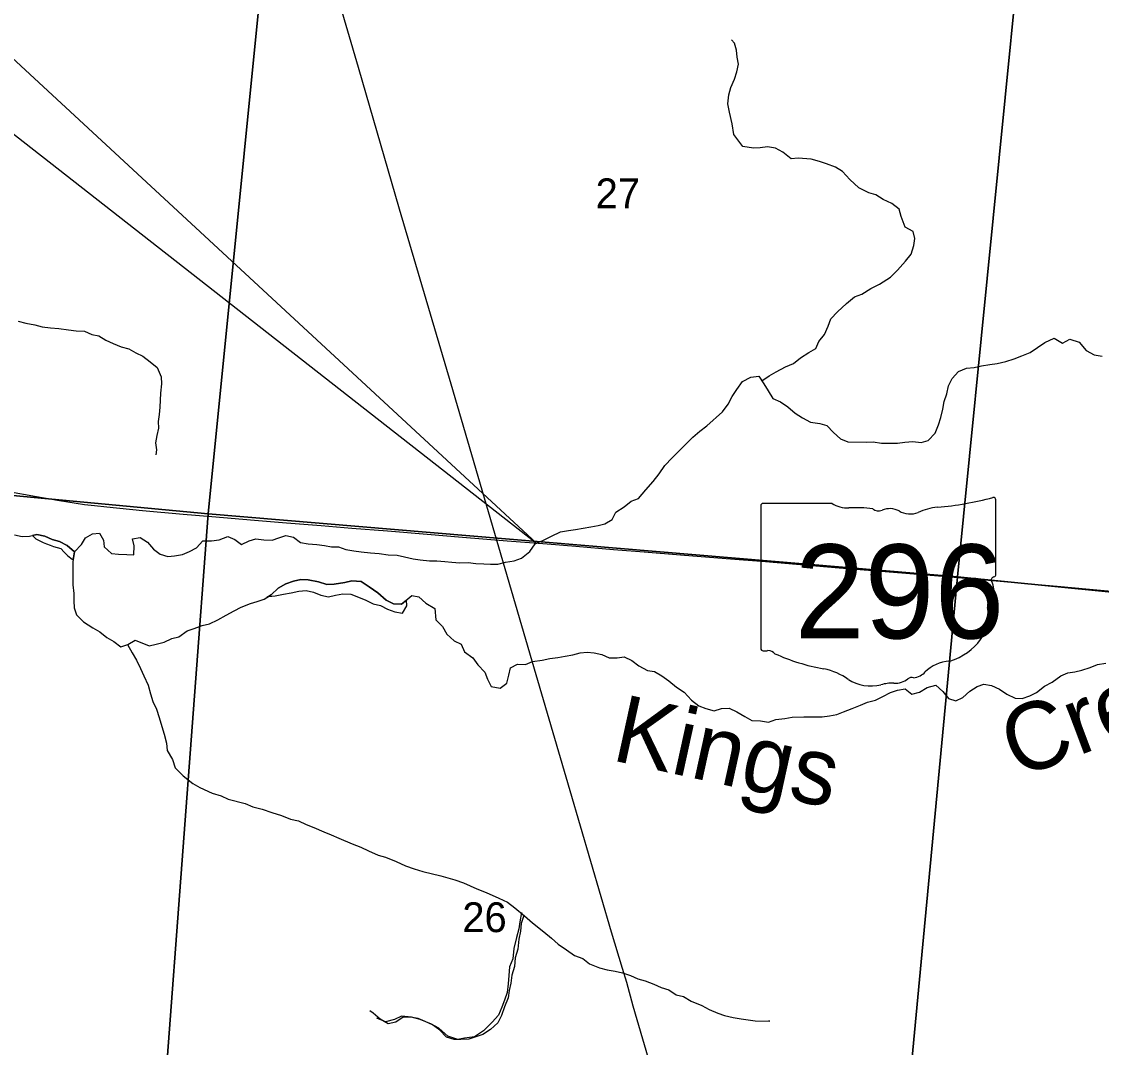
# Model space of a CAD drawing. Extents: x 831 to 1552, y 430 to 870.
# Drawn here: x 962.97 to 993.28, y 664.2 to 692.99 of the extents above; entities that cross this region are included whole.
import ezdxf

# ---------------------------------------------------------------- set-up
doc = ezdxf.new("R2010")
doc.units = 0
for name, color, linetype in [('GM_X_Corporation', 7, 'Continuous'), ('GM_X_Minor_Lake', 7, 'Continuous'), ('GM_X_Minor_River', 7, 'Continuous'), ('GM_X_Minor_River_Text', 7, 'Continuous'), ('GM_X_Rail_Line', 7, 'Continuous'), ('GM_X_Section_Text', 7, 'Continuous'), ('GM_X_State_Location', 7, 'Continuous'), ('GM_X_State_Route', 7, 'Continuous'), ('GM_X_State_Shield', 7, 'Continuous'), ('SH_Text', 7, 'Continuous')]:
    doc.layers.add(name, color=color, linetype=linetype)

msp = doc.modelspace()

# ---------------------------------------------------------------- linework, layer by layer
at = {"layer": 'GM_X_Corporation'}
for points in [[(970.228, 699.411), (968.2, 679.179), (947.656, 681.105), (949.612, 701.081)], [(970.228, 699.411), (991.236, 697.554), (989.239, 677.411), (968.2, 679.179)], [(1011.587, 695.769), (1009.676, 675.38), (989.239, 677.411), (991.236, 697.554)], [(947.656, 681.105), (968.2, 679.179), (966.669, 658.742), (945.863, 661.476)], [(968.2, 679.179), (989.239, 677.411), (987.314, 656.98), (966.669, 658.742)], [(989.239, 677.411), (1009.676, 675.38), (1007.707, 655.818), (987.314, 656.98)]]:
    msp.add_lwpolyline(points, close=True, dxfattribs=at)
at = {"layer": 'GM_X_Minor_Lake'}
for points in [[(964.455, 678.104), (964.248, 678.285), (964.031, 678.398), (963.828, 678.458), (963.618, 678.548), (963.391, 678.593), (963.275, 678.57)], [(963.275, 678.57), (963.371, 678.475), (963.568, 678.371), (963.664, 678.332), (963.765, 678.292), (963.863, 678.26), (963.968, 678.232), (964.068, 678.2), (964.159, 678.101), (964.256, 678.007), (964.352, 677.927), (964.411, 677.88)], [(964.411, 677.88), (964.455, 678.104)], [(973.769, 676.75), (973.633, 676.637), (973.406, 676.651), (973.204, 676.756), (972.968, 676.961), (972.722, 677.128), (972.498, 677.272), (972.241, 677.295), (972.042, 677.247), (971.737, 677.203), (971.532, 677.194), (971.299, 677.269), (971.012, 677.323), (970.808, 677.33), (970.601, 677.282), (970.387, 677.213), (970.171, 677.09), (969.968, 676.905), (969.848, 676.829)], [(969.848, 676.829), (969.898, 676.854), (970.088, 676.871), (970.317, 676.918), (970.531, 676.957), (970.753, 677.004), (970.958, 677.028), (971.162, 676.976), (971.364, 676.894), (971.583, 676.842), (971.781, 676.889), (971.988, 676.929), (972.207, 676.923), (972.425, 676.84), (972.627, 676.75), (972.837, 676.645), (973.04, 676.601), (973.242, 676.496), (973.445, 676.429), (973.657, 676.385), (973.776, 676.594), (973.769, 676.75)]]:
    msp.add_lwpolyline(points, dxfattribs=at)
at = {"layer": 'GM_X_Minor_River'}
for points in [[(983.743, 682.91), (983.946, 683.053), (984.146, 683.161), (984.408, 683.298), (984.631, 683.391), (984.833, 683.552), (985.065, 683.705), (985.258, 683.813), (985.348, 684.016), (985.505, 684.21), (985.603, 684.443), (985.685, 684.646), (985.865, 684.846), (986.122, 685.074), (986.348, 685.265), (986.548, 685.343), (986.803, 685.496), (987.049, 685.618), (987.359, 685.821), (987.554, 686.014), (987.781, 686.266), (987.932, 686.467), (988.007, 686.708), (988.035, 686.905), (987.988, 687.104), (987.771, 687.217), (987.651, 687.525), (987.596, 687.725), (987.396, 687.883), (987.149, 687.997), (986.948, 688.132), (986.745, 688.184), (986.468, 688.322), (986.217, 688.557), (986.011, 688.784), (985.809, 688.904), (985.562, 688.995), (985.366, 689.062), (985.125, 689.13), (984.762, 689.156), (984.564, 689.139), (984.334, 689.328), (984.125, 689.434), (983.906, 689.471), (983.7, 689.446), (983.51, 689.437), (983.208, 689.484), (982.96, 689.826), (982.915, 690.124), (982.834, 690.453), (982.788, 690.683), (982.818, 690.933), (982.877, 691.145), (982.975, 691.377), (983.042, 691.581), (983.086, 691.793), (983.054, 691.991), (983.037, 692.19), (982.982, 692.389), (982.893, 692.483)], [(962.868, 684.583), (963.087, 684.531), (963.336, 684.478), (963.547, 684.426), (963.781, 684.397), (964.008, 684.375), (964.28, 684.336), (964.5, 684.315), (964.735, 684.3), (964.937, 684.21), (965.133, 684.174), (965.327, 684.047), (965.537, 683.957), (965.762, 683.859), (965.973, 683.807), (966.174, 683.694), (966.369, 683.605), (966.576, 683.439), (966.777, 683.281), (966.883, 683.019), (966.893, 682.828), (966.862, 682.563), (966.85, 682.167), (966.829, 681.962), (966.801, 681.765), (966.81, 681.575), (966.759, 681.378), (966.73, 681.166), (966.755, 680.967), (966.736, 680.831)], [(975.716, 677.785), (975.944, 677.771), (976.133, 677.765), (976.331, 677.767), (976.552, 677.821), (976.796, 677.852), (977.003, 677.93), (977.229, 678.121), (977.379, 678.337), (977.595, 678.43), (977.841, 678.552), (978.095, 678.666), (978.316, 678.706), (978.514, 678.738), (978.728, 678.769), (978.942, 678.809), (979.148, 678.848), (979.339, 678.896), (979.54, 679.019), (979.644, 679.222), (979.876, 679.375), (980.078, 679.529), (980.285, 679.606), (980.49, 679.852), (980.694, 680.082), (980.867, 680.297), (981.018, 680.529), (981.23, 680.751), (981.425, 680.943), (981.613, 681.135), (981.808, 681.328), (982.003, 681.497), (982.204, 681.643), (982.641, 682.041), (982.799, 682.25), (982.912, 682.467), (983.039, 682.661), (983.205, 682.885), (983.436, 683.007), (983.657, 683.039), (983.802, 682.821), (983.926, 682.627), (984.056, 682.41), (984.273, 682.32), (984.474, 682.177), (984.681, 681.996), (984.89, 681.868), (985.107, 681.747), (985.371, 681.709), (985.567, 681.65), (985.759, 681.461), (985.951, 681.28), (986.161, 681.198), (986.677, 681.183), (986.867, 681.2), (987.101, 681.155), (987.336, 681.156), (987.556, 681.157), (987.755, 681.189), (987.983, 681.205), (988.217, 681.175), (988.416, 681.23), (988.612, 681.437), (988.702, 681.671), (988.769, 681.882), (988.821, 682.116), (988.866, 682.328), (988.94, 682.539), (988.985, 682.766), (989.089, 682.969), (989.262, 683.169), (989.485, 683.261), (989.706, 683.285), (989.912, 683.332), (990.148, 683.371), (990.354, 683.395), (990.598, 683.449), (990.828, 683.526), (991.043, 683.611), (991.274, 683.703), (991.483, 683.841), (991.692, 683.987), (991.954, 684.109), (992.185, 683.965), (992.393, 684.073), (992.656, 683.989), (992.847, 683.763), (993.071, 683.642), (993.297, 683.597)], [(962.769, 678.588), (962.987, 678.536), (963.185, 678.553), (963.391, 678.593), (963.618, 678.548), (963.828, 678.458), (964.031, 678.398), (964.248, 678.285), (964.455, 678.104), (964.651, 678.312), (964.763, 678.506), (964.955, 678.615), (965.153, 678.632), (965.269, 678.438), (965.286, 678.247), (965.493, 678.058), (965.69, 678.045), (965.918, 678.03), (966.115, 678.025), (966.13, 678.275), (966.082, 678.475), (966.296, 678.514), (966.497, 678.379), (966.666, 678.183), (966.859, 678.041), (967.07, 677.981), (967.26, 677.998), (967.481, 678.03), (967.681, 678.115), (967.874, 678.224), (968.054, 678.416), (968.297, 678.417), (968.51, 678.441), (968.756, 678.54), (968.95, 678.451), (969.144, 678.315), (969.352, 678.416), (969.543, 678.471), (969.762, 678.442), (969.997, 678.435), (970.189, 678.505), (970.388, 678.568), (970.6, 678.524), (970.792, 678.366), (971.012, 678.336), (971.254, 678.314), (971.473, 678.284), (971.669, 678.248), (971.859, 678.25), (972.069, 678.175), (972.296, 678.138), (972.5, 678.109), (972.757, 678.079), (973.007, 678.064), (973.257, 678.026), (973.507, 678.011), (973.718, 677.966), (973.959, 677.914), (974.156, 677.885), (974.42, 677.854), (974.625, 677.856), (974.845, 677.834), (975.042, 677.821), (975.269, 677.799), (975.504, 677.807), (975.716, 677.785)], [(964.455, 678.104), (964.401, 677.832), (964.409, 677.588), (964.403, 677.375), (964.405, 677.184), (964.436, 676.94), (964.43, 676.734), (964.447, 676.536), (964.51, 676.344), (964.709, 676.148), (964.97, 675.98), (965.163, 675.86), (965.356, 675.702), (965.558, 675.589), (965.751, 675.447), (965.95, 675.509), (966.159, 675.632), (966.548, 675.469), (966.74, 675.516), (966.969, 675.57), (967.185, 675.678), (967.376, 675.726), (967.616, 675.894), (967.815, 675.956), (968.038, 676.041), (968.244, 676.088), (968.475, 676.203), (968.706, 676.334), (968.938, 676.456), (969.13, 676.557), (969.391, 676.656), (969.583, 676.711), (969.775, 676.782), (969.968, 676.905), (970.171, 677.09), (970.387, 677.213), (970.601, 677.282), (970.808, 677.33), (971.012, 677.323), (971.299, 677.269), (971.532, 677.194), (971.737, 677.203), (972.042, 677.247), (972.241, 677.295), (972.498, 677.272), (972.722, 677.128), (972.968, 676.961), (973.204, 676.756), (973.406, 676.651), (973.633, 676.637), (973.921, 676.879), (974.118, 676.843), (974.31, 676.67), (974.564, 676.517), (974.592, 676.204), (974.784, 676.016), (974.899, 675.799), (975.106, 675.61), (975.301, 675.513), (975.401, 675.305), (975.631, 675.13), (975.777, 674.936), (975.969, 674.732), (976.047, 674.539), (976.147, 674.331), (976.396, 674.278), (976.59, 674.424), (976.642, 674.643), (976.693, 674.855), (976.886, 674.956), (977.113, 674.949), (977.306, 675.027), (977.58, 675.065), (977.794, 675.119), (978.022, 675.143), (978.228, 675.183), (978.442, 675.214), (978.641, 675.277), (978.839, 675.294), (979.043, 675.273), (979.254, 675.228), (979.464, 675.131), (979.684, 675.132), (979.882, 675.164), (980.092, 675.059), (980.292, 674.908), (980.532, 674.779), (980.728, 674.75), (980.937, 674.63), (981.138, 674.487), (981.353, 674.313), (981.561, 674.17), (981.775, 673.95), (981.975, 673.784), (982.17, 673.71), (982.411, 673.649), (982.61, 673.712), (982.831, 673.721), (983.04, 673.615), (983.264, 673.487), (983.466, 673.374)], [(965.942, 675.507), (966.072, 675.277), (966.188, 675.068), (966.302, 674.836), (966.395, 674.628), (966.524, 674.365), (966.585, 674.127), (966.655, 673.912), (966.755, 673.696), (966.831, 673.458), (966.9, 673.204), (966.969, 672.989), (967.038, 672.743), (967.055, 672.537), (967.207, 672.281), (967.276, 672.043), (967.505, 671.823), (967.771, 671.602), (967.966, 671.497), (968.318, 671.335), (968.566, 671.259), (968.761, 671.169), (969.243, 671.048), (969.46, 670.95), (969.716, 670.889), (969.994, 670.79), (970.258, 670.713), (970.513, 670.607), (970.739, 670.562), (970.956, 670.456), (971.174, 670.374), (971.451, 670.251), (971.653, 670.162), (971.871, 670.071), (972.246, 669.916), (972.486, 669.817), (972.703, 669.719), (972.98, 669.597), (973.183, 669.537), (973.484, 669.422), (973.746, 669.3), (973.986, 669.209), (974.234, 669.14), (974.739, 669.019), (975.123, 668.901), (975.371, 668.817), (975.746, 668.654), (976.008, 668.547), (976.36, 668.392), (976.608, 668.278), (976.815, 668.119), (977.082, 667.89), (977.304, 667.693), (977.623, 667.448), (977.838, 667.266), (978.03, 667.101), (978.261, 666.934), (978.484, 666.775), (978.717, 666.692), (978.91, 666.549), (979.187, 666.434), (979.406, 666.374), (979.625, 666.337), (979.836, 666.293), (980.061, 666.218), (980.264, 666.12), (980.467, 666.068), (980.715, 665.97), (980.917, 665.88), (981.135, 665.82), (981.336, 665.677), (981.547, 665.625), (981.763, 665.497), (982.056, 665.374), (982.265, 665.261), (982.505, 665.162), (982.7, 665.096), (982.941, 665.035), (983.16, 664.998), (983.357, 664.969), (983.561, 664.948), (983.971, 664.936), (983.941, 664.944)], [(983.466, 673.374), (983.708, 673.367), (983.935, 673.33), (984.142, 673.4), (984.393, 673.43), (984.592, 673.47), (984.926, 673.475), (985.176, 673.476), (985.434, 673.475), (985.648, 673.507), (985.846, 673.547), (986.038, 673.617), (986.276, 673.709), (986.514, 673.809), (986.714, 673.887), (986.936, 673.941), (987.144, 674.049), (987.359, 674.157), (987.551, 674.227), (987.765, 674.259), (987.958, 674.116), (988.172, 674.171), (988.381, 674.302), (988.633, 674.363), (988.825, 674.189), (988.986, 673.994), (989.189, 673.927), (989.382, 674.02), (989.584, 674.197), (989.786, 674.328), (989.977, 674.391), (990.189, 674.354), (990.413, 674.256), (990.622, 674.113), (990.854, 673.999), (991.051, 673.994), (991.266, 674.071), (991.458, 674.157), (991.676, 674.34), (991.891, 674.448), (992.139, 674.624), (992.332, 674.717), (992.53, 674.741), (992.729, 674.789), (992.959, 674.866), (993.166, 674.943), (993.402, 674.982)], [(977.065, 667.905), (976.985, 667.68), (976.971, 667.46), (976.926, 667.233), (976.895, 666.959), (976.82, 666.718), (976.798, 666.475), (976.73, 666.225), (976.7, 665.998), (976.657, 665.801), (976.628, 665.589), (976.522, 665.341), (976.439, 665.092), (976.334, 664.889), (976.131, 664.705), (975.915, 664.559), (975.715, 664.496), (975.524, 664.433), (975.296, 664.417), (975.106, 664.423), (974.896, 664.49), (974.704, 664.686), (974.503, 664.829), (974.293, 664.927), (974.099, 665.009), (973.887, 665.046), (973.675, 665.044), (973.473, 664.906), (973.252, 664.859), (973.028, 664.988), (972.835, 665.161), (972.746, 665.224)], [(976.999, 667.983), (976.951, 667.726), (976.925, 667.53), (976.854, 667.288), (976.788, 666.978), (976.754, 666.69), (976.659, 666.457), (976.64, 666.214), (976.622, 665.98), (976.595, 665.737), (976.524, 665.526), (976.445, 665.33), (976.351, 665.104), (976.174, 664.909), (975.936, 664.663), (975.676, 664.5), (975.403, 664.458), (975.213, 664.423), (974.935, 664.518), (974.674, 664.735), (974.471, 664.851), (974.156, 664.985), (973.907, 665.049), (973.628, 665.076), (973.437, 664.981), (973.179, 664.916), (972.939, 665.018)]]:
    msp.add_lwpolyline(points, dxfattribs=at)
at = {"layer": 'GM_X_Rail_Line'}
msp.add_lwpolyline([(981.517, 660.634), (980.134, 665.355), (979.958, 666.026), (979.838, 666.41), (979.526, 667.436), (978.364, 671.402), (977.298, 675.036), (975.025, 682.814), (973.576, 687.723), (972.42, 691.703), (968.237, 705.956)], dxfattribs=at)
at = {"layer": 'GM_X_State_Route'}
msp.add_lwpolyline([(962.551, 679.812), (963.384, 679.658), (963.972, 679.557), (964.5, 679.475), (964.737, 679.441), (965.013, 679.408), (965.362, 679.368), (966.364, 679.27), (967.502, 679.168), (968.307, 679.099), (969.507, 678.993), (970.399, 678.92), (971.378, 678.844), (972.232, 678.775), (973.236, 678.696), (974.351, 678.606), (975.342, 678.523), (976.592, 678.422), (977.72, 678.329), (978.525, 678.268), (979.578, 678.178), (980.445, 678.107), (981.46, 678.024), (982.748, 677.917), (983.851, 677.834), (985.919, 677.662), (987.443, 677.538), (988.817, 677.423), (990.539, 677.275), (992.135, 677.132), (992.94, 677.061), (994.685, 676.902)], dxfattribs=at)
at = {"layer": 'GM_X_State_Shield'}
for p, q in [((990.311, 677.474), (990.311, 679.567)), ((983.72, 679.399), (983.72, 675.397)), ((985.715, 679.468), (983.785, 679.468)), ((990.311, 677.474), (990.311, 677.474))]:
    msp.add_line(p, q, dxfattribs=at)
for centre, major_axis, start_param, end_param in [((987.963, 684.925), (6.99, 0), 4.814394, 5.042369), ((990.238, 679.576), (0.0734, 0), 6.141152, 7.989035), ((983.795, 679.408), (0.0764, 0), 1.712693, 3.28349), ((986.175, 679.933), (0.741, 0), 4.042523, 4.731795), ((986.42, 677.221), (2.659, 0), 1.404758, 1.657858), ((987.024, 679.428), (0.214, 0), 3.836095, 5.185415), ((987.338, 678.966), (0.444, 0), 0.950623, 2.079405), ((987.911, 679.6), (0.534, 0), 4.081561, 5.145723), ((988.855, 678.246), (1.406, 0), 1.699011, 2.107814), ((990.294, 677.32), (0.114, 0), 1.883978, 3.671073), ((990.233, 677.465), (0.0785, 0), 5.05454, 6.418171), ((989.572, 677.055), (0.682, 0), 5.934695, 6.695948), ((990.574, 676.597), (0.496, 0), 2.387724, 3.262537), ((988.355, 676.331), (1.748, 0), 5.101752, 6.440018), ((983.796, 675.388), (0.077, 0), 3.00124, 4.508301), ((983.808, 675.798), (0.588, 0), 4.665946, 4.897461), ((983.928, 675.166), (0.212, 0), 0.519207, 1.627899), ((986.604, 678.762), (5.048, 0), 4.195997, 4.488961), ((989.092, 674.273), (0.958, 0), 1.647645, 2.488434), ((985.099, 673.599), (1.579, 0), 0.823519, 1.323587), ((987.879, 675.009), (0.565, 0), 4.937069, 5.64225), ((986.808, 675.146), (1.002, 0), 4.026481, 4.996735), ((987.387, 673.762), (0.824, 0), 1.495662, 1.94098), ((987.46, 674.846), (0.534, 0), 4.691044, 5.507374), ((987.943, 674.459), (0.15, 0), 1.147584, 2.315152)]:
    msp.add_ellipse(centre, major_axis=major_axis, ratio=0.8, start_param=start_param, end_param=end_param, dxfattribs=at)
at = {"layer": 'SH_Text'}
msp.add_lwpolyline([(977.418, 678.354), (911.466, 739.393), (911.466, 729.958)], close=True, dxfattribs=at)

# ---------------------------------------------------------------- texts
at = {"layer": 'GM_X_Minor_River_Text'}
for s, rotation, p in [('Creek', 20.6145, (990.912, 671.737)), ('Kings', 347.6289, (979.488, 672.268))]:
    msp.add_text(s, height=1.8939, rotation=rotation, dxfattribs=at).set_placement(p)
at = {"layer": 'GM_X_Section_Text'}
for s, p in [('27', (979.079, 687.752)), ('26', (975.338, 667.435))]:
    msp.add_text(s, height=0.8371, rotation=0, dxfattribs=at).set_placement(p)
at = {"layer": 'GM_X_State_Location'}
for s, p in [('s', (986.942, 677.132)), ('r', (986.941, 677.132))]:
    msp.add_text(s, height=0.00379, dxfattribs=at).set_placement(p)
msp.add_text('296', height=0.00379, rotation=0, dxfattribs=at).set_placement((985.604, 676.856))
at = {"layer": 'GM_X_State_Shield'}
msp.add_text('296', height=2.6367, dxfattribs=at).set_placement((984.668, 675.679))

doc.saveas('drawing.dxf')
